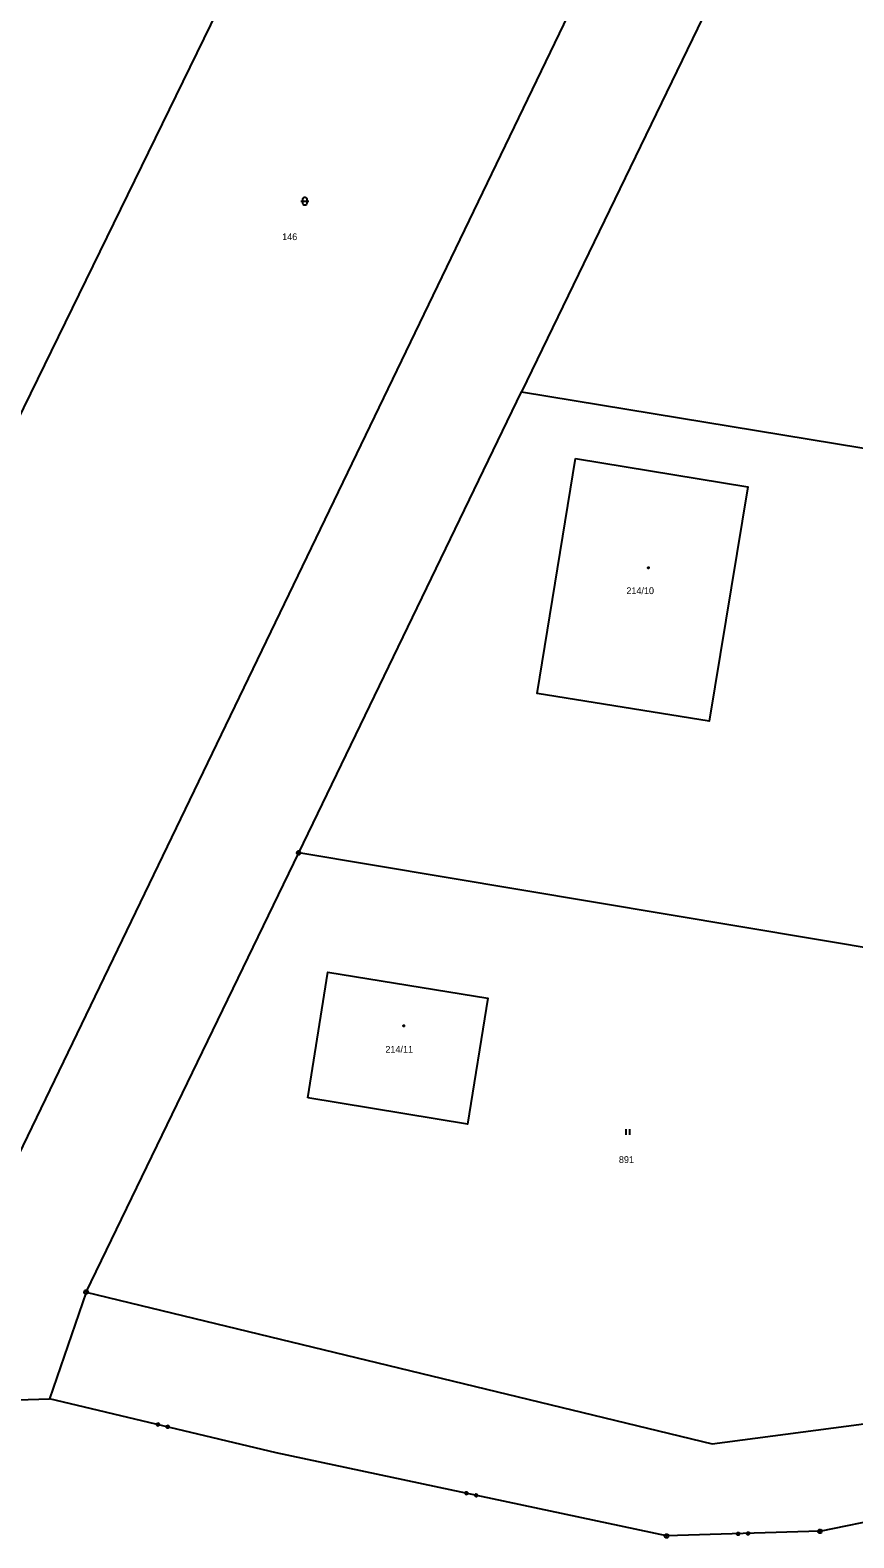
# Model space of a CAD drawing. Extents: x -871430 to -870620, y -1010094 to -1009649.
# Drawn here: x -870763.8 to -870712, y -1010046.1 to -1009951.2 of the extents above; entities that cross this region are included whole.
import ezdxf

# ---------------------------------------------------------------- set-up
doc = ezdxf.new("R2010")
doc.units = 0
for name, color, linetype in [('Vrstva 1', 7, 'Continuous'), ('Vrstva 2', 7, 'Continuous'), ('Vrstva 3', 7, 'Continuous'), ('Vrstva 5', 7, 'Continuous'), ('Vrstva 8', 7, 'Continuous')]:
    doc.layers.add(name, color=color, linetype=linetype)

msp = doc.modelspace()

# ---------------------------------------------------------------- linework, layer by layer
at = {"layer": 'Vrstva 1'}
for p, q in [((-870768.7, -1009984.15), (-870742.3, -1009930.08)), ((-870713.4, -1009933.7), (-870732.89, -1009974)), ((-870767.95, -1010029.06), (-870723.23, -1009936.33)), ((-870746.92, -1010003.01), (-870732.89, -1009974)), ((-870732.89, -1009974), (-870683.39, -1009982.15)), ((-870760.31, -1010030.66), (-870746.92, -1010003.01)), ((-870697.36, -1010011.31), (-870746.92, -1010003.01)), ((-870760.31, -1010030.66), (-870762.6, -1010037.37)), ((-870760.31, -1010030.66), (-870720.9, -1010040.22)), ((-870787.07, -1010038.2), (-870762.6, -1010037.37)), ((-870748.33, -1010040.77), (-870762.6, -1010037.37)), ((-870720.9, -1010040.22), (-870710.55, -1010038.85)), ((-870723.76, -1010046.01), (-870748.33, -1010040.77)), ((-870714.11, -1010045.72), (-870687.95, -1010040.3)), ((-870714.11, -1010045.72), (-870723.76, -1010046.01))]:
    msp.add_line(p, q, dxfattribs=at)
for points in [[(-870729.49, -1009978.18), (-870718.65, -1009979.98), (-870721.08, -1009994.73), (-870731.92, -1009992.98), (-870729.49, -1009978.18)], [(-870746.35, -1010018.43), (-870745.08, -1010010.52), (-870735.01, -1010012.16), (-870736.3, -1010020.08), (-870746.35, -1010018.43)], [(-870755.831, -1010039.065), (-870755.867, -1010039.008), (-870755.851, -1010038.942), (-870755.794, -1010038.907), (-870755.728, -1010038.923), (-870755.693, -1010038.98), (-870755.708, -1010039.045), (-870755.766, -1010039.081), (-870755.831, -1010039.065), (-870755.822, -1010039.057), (-870755.763, -1010039.071), (-870755.739, -1010039.056), (-870755.837, -1010039.033), (-870755.851, -1010039.009), (-870755.715, -1010039.041), (-870755.711, -1010039.022), (-870755.847, -1010038.989), (-870755.842, -1010038.97), (-870755.706, -1010039.002), (-870755.701, -1010038.983), (-870755.837, -1010038.951), (-870755.813, -1010038.936), (-870755.716, -1010038.959), (-870755.731, -1010038.935), (-870755.789, -1010038.921)], [(-870755.223, -1010039.21), (-870755.258, -1010039.153), (-870755.243, -1010039.087), (-870755.186, -1010039.052), (-870755.12, -1010039.067), (-870755.085, -1010039.124), (-870755.1, -1010039.19), (-870755.158, -1010039.225), (-870755.223, -1010039.21), (-870755.219, -1010039.201), (-870755.16, -1010039.214), (-870755.136, -1010039.2), (-870755.233, -1010039.177), (-870755.248, -1010039.152), (-870755.112, -1010039.185), (-870755.107, -1010039.165), (-870755.244, -1010039.133), (-870755.239, -1010039.114), (-870755.103, -1010039.146), (-870755.098, -1010039.126), (-870755.234, -1010039.094), (-870755.21, -1010039.079), (-870755.113, -1010039.102), (-870755.128, -1010039.078), (-870755.186, -1010039.064)], [(-870736.411, -1010043.394), (-870736.448, -1010043.337), (-870736.434, -1010043.271), (-870736.377, -1010043.235), (-870736.311, -1010043.249), (-870736.275, -1010043.305), (-870736.289, -1010043.371), (-870736.345, -1010043.408), (-870736.411, -1010043.394), (-870736.402, -1010043.385), (-870736.343, -1010043.398), (-870736.319, -1010043.382), (-870736.417, -1010043.362), (-870736.433, -1010043.338), (-870736.296, -1010043.367), (-870736.292, -1010043.348), (-870736.428, -1010043.318), (-870736.424, -1010043.299), (-870736.287, -1010043.328), (-870736.283, -1010043.308), (-870736.42, -1010043.279), (-870736.396, -1010043.264), (-870736.299, -1010043.285), (-870736.314, -1010043.261), (-870736.373, -1010043.248)], [(-870735.8, -1010043.524), (-870735.837, -1010043.468), (-870735.823, -1010043.402), (-870735.766, -1010043.365), (-870735.7, -1010043.379), (-870735.664, -1010043.436), (-870735.678, -1010043.502), (-870735.734, -1010043.538), (-870735.8, -1010043.524), (-870735.796, -1010043.515), (-870735.737, -1010043.527), (-870735.713, -1010043.512), (-870735.811, -1010043.491), (-870735.826, -1010043.467), (-870735.689, -1010043.497), (-870735.685, -1010043.477), (-870735.822, -1010043.448), (-870735.818, -1010043.428), (-870735.681, -1010043.458), (-870735.677, -1010043.438), (-870735.814, -1010043.409), (-870735.79, -1010043.393), (-870735.692, -1010043.414), (-870735.708, -1010043.391), (-870735.766, -1010043.378)], [(-870719.29, -1010045.956), (-870719.339, -1010045.91), (-870719.341, -1010045.842), (-870719.295, -1010045.793), (-870719.227, -1010045.791), (-870719.178, -1010045.837), (-870719.176, -1010045.905), (-870719.222, -1010045.954), (-870719.29, -1010045.956), (-870719.283, -1010045.946), (-870719.223, -1010045.944), (-870719.203, -1010045.923), (-870719.303, -1010045.926), (-870719.324, -1010045.907), (-870719.184, -1010045.903), (-870719.185, -1010045.883), (-870719.325, -1010045.887), (-870719.325, -1010045.867), (-870719.185, -1010045.863), (-870719.186, -1010045.843), (-870719.326, -1010045.847), (-870719.306, -1010045.826), (-870719.206, -1010045.823), (-870719.227, -1010045.804), (-870719.287, -1010045.806)], [(-870718.665, -1010045.937), (-870718.714, -1010045.891), (-870718.716, -1010045.823), (-870718.67, -1010045.774), (-870718.603, -1010045.772), (-870718.554, -1010045.818), (-870718.552, -1010045.886), (-870718.598, -1010045.935), (-870718.665, -1010045.937), (-870718.663, -1010045.927), (-870718.603, -1010045.925), (-870718.584, -1010045.904), (-870718.684, -1010045.907), (-870718.704, -1010045.888), (-870718.564, -1010045.884), (-870718.565, -1010045.864), (-870718.705, -1010045.868), (-870718.705, -1010045.848), (-870718.565, -1010045.844), (-870718.566, -1010045.824), (-870718.706, -1010045.828), (-870718.687, -1010045.807), (-870718.587, -1010045.804), (-870718.607, -1010045.785), (-870718.667, -1010045.787)]]:
    msp.add_lwpolyline(points, dxfattribs=at)
at = {"layer": 'Vrstva 3'}
for p, q in [((-870726.335, -1010020.395), (-870726.335, -1010020.77)), ((-870726.085, -1010020.77), (-870726.085, -1010020.395))]:
    msp.add_line(p, q, dxfattribs=at)
for points in [[(-870746.79, -1009961.99), (-870746.472, -1009961.99), (-870746.29, -1009961.99)], [(-870746.665, -1009961.865), (-870746.64, -1009961.792), (-870746.578, -1009961.747), (-870746.5, -1009961.747), (-870746.438, -1009961.792), (-870746.413, -1009961.865), (-870746.413, -1009962.115), (-870746.438, -1009962.188), (-870746.5, -1009962.232), (-870746.578, -1009962.232), (-870746.64, -1009962.188), (-870746.665, -1009962.115), (-870746.665, -1009961.865)]]:
    msp.add_lwpolyline(points, dxfattribs=at)
at = {"layer": 'Vrstva 5'}
for points in [[(-870724.91, -1009985.028), (-870724.885, -1009985.032), (-870724.872, -1009985.055), (-870724.868, -1009985.07), (-870724.872, -1009985.092), (-870724.893, -1009985.11), (-870724.91, -1009985.112), (-870724.932, -1009985.105), (-870724.948, -1009985.09), (-870724.952, -1009985.07), (-870724.948, -1009985.048), (-870724.928, -1009985.03), (-870724.91, -1009985.028)], [(-870740.31, -1010013.858), (-870740.285, -1010013.862), (-870740.273, -1010013.885), (-870740.268, -1010013.9), (-870740.273, -1010013.922), (-870740.293, -1010013.94), (-870740.31, -1010013.942), (-870740.332, -1010013.935), (-870740.348, -1010013.92), (-870740.352, -1010013.9), (-870740.348, -1010013.878), (-870740.328, -1010013.86), (-870740.31, -1010013.858)]]:
    msp.add_lwpolyline(points, dxfattribs=at)
at = {"layer": 'Vrstva 8'}
for p, q in [((-870746.932, -1010003.01), (-870746.908, -1010003.01)), ((-870760.322, -1010030.66), (-870760.298, -1010030.66)), ((-870714.122, -1010045.72), (-870714.098, -1010045.72)), ((-870723.772, -1010046.01), (-870723.748, -1010046.01))]:
    msp.add_line(p, q, dxfattribs=at)
for points in [[(-870746.883, -1010002.89), (-870746.82, -1010002.938), (-870746.795, -1010003.01), (-870746.82, -1010003.082), (-870746.883, -1010003.13), (-870746.958, -1010003.13), (-870747.02, -1010003.082), (-870747.045, -1010003.01), (-870747.02, -1010002.938), (-870746.958, -1010002.89), (-870746.883, -1010002.89)], [(-870760.273, -1010030.54), (-870760.21, -1010030.588), (-870760.185, -1010030.66), (-870760.21, -1010030.732), (-870760.273, -1010030.78), (-870760.348, -1010030.78), (-870760.41, -1010030.732), (-870760.435, -1010030.66), (-870760.41, -1010030.588), (-870760.348, -1010030.54), (-870760.273, -1010030.54)], [(-870723.722, -1010045.89), (-870723.66, -1010045.938), (-870723.635, -1010046.01), (-870723.66, -1010046.082), (-870723.722, -1010046.13), (-870723.798, -1010046.13), (-870723.86, -1010046.082), (-870723.885, -1010046.01), (-870723.86, -1010045.938), (-870723.798, -1010045.89), (-870723.722, -1010045.89)], [(-870714.072, -1010045.6), (-870714.01, -1010045.648), (-870713.985, -1010045.72), (-870714.01, -1010045.792), (-870714.072, -1010045.84), (-870714.148, -1010045.84), (-870714.21, -1010045.792), (-870714.235, -1010045.72), (-870714.21, -1010045.648), (-870714.148, -1010045.6), (-870714.072, -1010045.6)]]:
    msp.add_lwpolyline(points, dxfattribs=at)

# ---------------------------------------------------------------- texts
at = {"layer": 'Vrstva 2'}
for s, p in [('146', (-870747.962, -1009964.44)), ('214/10', (-870726.294, -1009986.722)), ('214/11', (-870741.464, -1010015.592)), ('891', (-870726.765, -1010022.532))]:
    msp.add_text(s, height=0.425, dxfattribs=at).set_placement(p)

doc.saveas('drawing.dxf')
